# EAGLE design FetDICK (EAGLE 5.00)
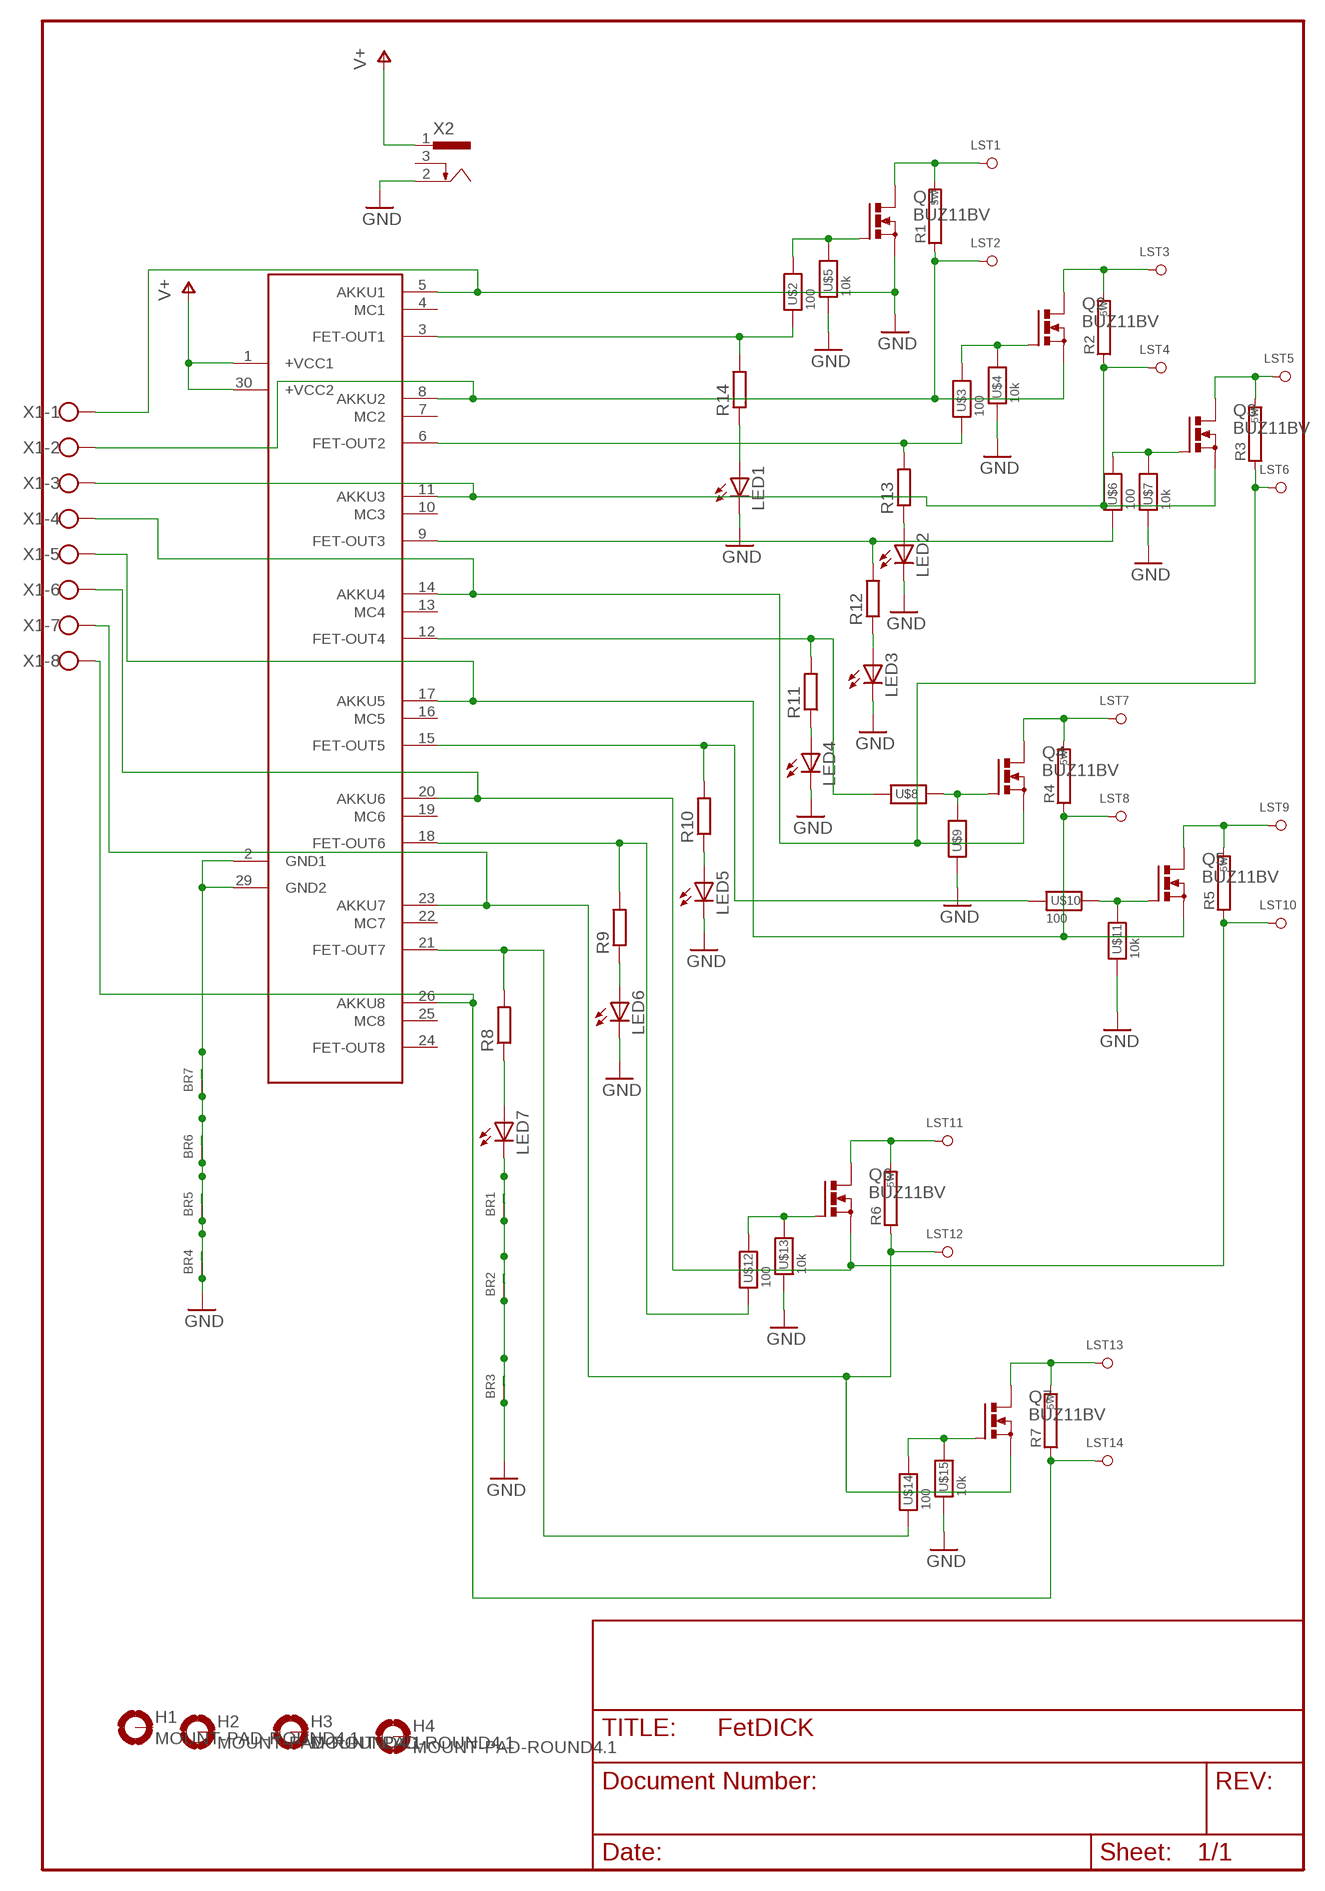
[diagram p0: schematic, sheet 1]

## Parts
BR1  BRUE3E  [BRUE3E]
BR2  BRUE3E  [BRUE3E]
BR3  BRUE3E  [BRUE3E]
BR4  BRUE3E  [BRUE3E]
BR5  BRUE3E  [BRUE3E]
BR6  BRUE3E  [BRUE3E]
BR7  BRUE3E  [BRUE3E]
H1  MOUNT-PAD-ROUND4.1  [4,1-PAD]
H2  MOUNT-PAD-ROUND4.1  [4,1-PAD]
H3  MOUNT-PAD-ROUND4.1  [4,1-PAD]
H4  MOUNT-PAD-ROUND4.1  [4,1-PAD]
LED1  LED5MM  [LED5MM]
LED2  LED5MM  [LED5MM]
LED3  LED5MM  [LED5MM]
LED4  LED5MM  [LED5MM]
LED5  LED5MM  [LED5MM]
LED6  LED5MM  [LED5MM]
LED7  LED5MM  [LED5MM]
LST1  LOETST02  [LOETST02]
LST2  LOETST02  [LOETST02]
LST3  LOETST02  [LOETST02]
LST4  LOETST02  [LOETST02]
LST5  LOETST02  [LOETST02]
LST6  LOETST02  [LOETST02]
LST7  LOETST02  [LOETST02]
LST8  LOETST02  [LOETST02]
LST9  LOETST02  [LOETST02]
LST10  LOETST02  [LOETST02]
LST11  LOETST02  [LOETST02]
LST12  LOETST02  [LOETST02]
LST13  LOETST02  [LOETST02]
LST14  LOETST02  [LOETST02]
Q1  BUZ11BV  [TO220BV]
Q2  BUZ11BV  [TO220BV]
Q3  BUZ11BV  [TO220BV]
Q4  BUZ11BV  [TO220BV]
Q5  BUZ11BV  [TO220BV]
Q6  BUZ11BV  [TO220BV]
Q7  BUZ11BV  [TO220BV]
R1  208R  [208R]
R2  208R  [208R]
R3  208R  [208R]
R4  208R  [208R]
R5  208R  [208R]
R6  208R  [208R]
R7  208R  [208R]
R8  R-EU_0207/2V  [0207/2V]
R9  R-EU_0207/2V  [0207/2V]
R10  R-EU_0207/2V  [0207/2V]
R11  R-EU_0207/2V  [0207/2V]
R12  R-EU_0207/2V  [0207/2V]
R13  R-EU_0207/2V  [0207/2V]
R14  R-EU_0207/2V  [0207/2V]
U$1  BALANCER1  [1X30]
U$2  100  R4E  [R-4E]
U$3  100  R4E  [R-4E]
U$4  10k  R4E  [R-4E]
U$5  10k  R4E  [R-4E]
U$6  100  R4E  [R-4E]
U$7  10k  R4E  [R-4E]
U$8  R4E  [R-4E]
U$9  R4E  [R-4E]
U$10  100  R4E  [R-4E]
U$11  10k  R4E  [R-4E]
U$12  100  R4E  [R-4E]
U$13  10k  R4E  [R-4E]
U$14  100  R4E  [R-4E]
U$15  10k  R4E  [R-4E]
X1  W237-08P  [W237-8P]
X2  733980-62  [733980-62]

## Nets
GND: BR1.1 BR1.2 BR2.1 BR2.2 BR3.1 BR3.2 BR4.1 BR4.2 BR5.1 BR5.2 BR6.1 BR6.2 BR7.1 BR7.2 LED1.K(C) LED2.K(C) LED3.K(C) LED4.K(C) LED5.K(C) LED6.K(C) LED7.K(C) Q1.S U$1.2(GND1) U$1.5(AKKU1) U$1.29(GND2) U$4.1 U$5.1 U$7.1 U$9.1 U$11.1 U$13.1 U$15.1 X1.1 X2.2
N$1: R14.2 U$1.3(FET-OUT1) U$2.1
N$2: Q1.G U$2.2 U$5.2
N$3: LED1.A R14.1
N$4: LST1.1 Q1.D R1.2
N$5: R13.2 U$1.6(FET-OUT2) U$3.1
N$6: LST2.1 Q2.S R1.1 U$1.8(AKKU2) X1.2
N$7: Q2.G U$3.2 U$4.2
N$9: LST3.1 Q2.D R2.2
N$10: LST4.1 Q3.S R2.1 U$1.11(AKKU3) X1.3
N$11: R12.2 U$1.9(FET-OUT3) U$6.1
N$12: Q3.G U$6.2 U$7.2
N$13: LED2.A R13.1
N$14: LST5.1 Q3.D R3.2
N$15: LST6.1 Q4.S R3.1 U$1.14(AKKU4) X1.4
N$16: R11.2 U$1.12(FET-OUT4) U$8.1
N$17: Q4.G U$8.2 U$9.2
N$19: LST7.1 Q4.D R4.2
N$20: LST8.1 Q5.S R4.1 U$1.17(AKKU5) X1.5
N$21: R10.2 U$1.15(FET-OUT5) U$10.1
N$22: Q5.G U$10.2 U$11.2
N$23: LED3.A R12.1
N$24: LST9.1 Q5.D R5.2
N$25: R8.2 U$1.21(FET-OUT7) U$14.1
N$26: R9.2 U$1.18(FET-OUT6) U$12.1
N$27: Q6.G U$12.2 U$13.2
N$28: LST10.1 Q6.S R5.1 U$1.20(AKKU6) X1.6
N$29: LST11.1 Q6.D R6.2
N$31: Q7.G U$14.2 U$15.2
N$32: LST12.1 Q7.S R6.1 U$1.23(AKKU7) X1.7
N$33: LST13.1 Q7.D R7.2
N$34: LST14.1 R7.1 U$1.26(AKKU8) X1.8
N$35: LED4.A R11.1
N$36: LED5.A R10.1
N$37: LED6.A R9.1
N$38: LED7.A R8.1
V+: U$1.1(+VCC1) U$1.30(+VCC2) X2.1
Unconnected: H1.B4,1(MOUNT) H2.B4,1(MOUNT) H3.B4,1(MOUNT) H4.B4,1(MOUNT) U$1.4(MC1) U$1.7(MC2) U$1.10(MC3) U$1.13(MC4) U$1.16(MC5) U$1.19(MC6) U$1.22(MC7) U$1.24(FET-OUT8) U$1.25(MC8) X2.3

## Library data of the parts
BR1-BR7 = raf_discrete:BRUE3E
H1-H4 = holes:MOUNT-PAD-ROUND: MOUNTING PAD, round
LED1-LED7 = led:LED: LED
LST1-LST14 = raf_connector:LOETST02
Q1-Q7 = transistor-power:BUZ11: N-CHANNEL MOS FET
R1-R7 = R-PWR:208R
R8-R14 = rcl:R-EU_: RESISTOR, European symbol
U$1 = balancer-mega8:BALANCER1
U$2-U$15 = raf_discrete:R: Standard-Widerstand 1/4W, Baugrößen 4e - 8e
X1 = con-wago-508:W237-08P: WAGO SREW CLAMP
X2 = con-conrad:73398?: FEMALE PRINT CONNECTOR Niedervolt-Steckverbinder Distributor Conrad

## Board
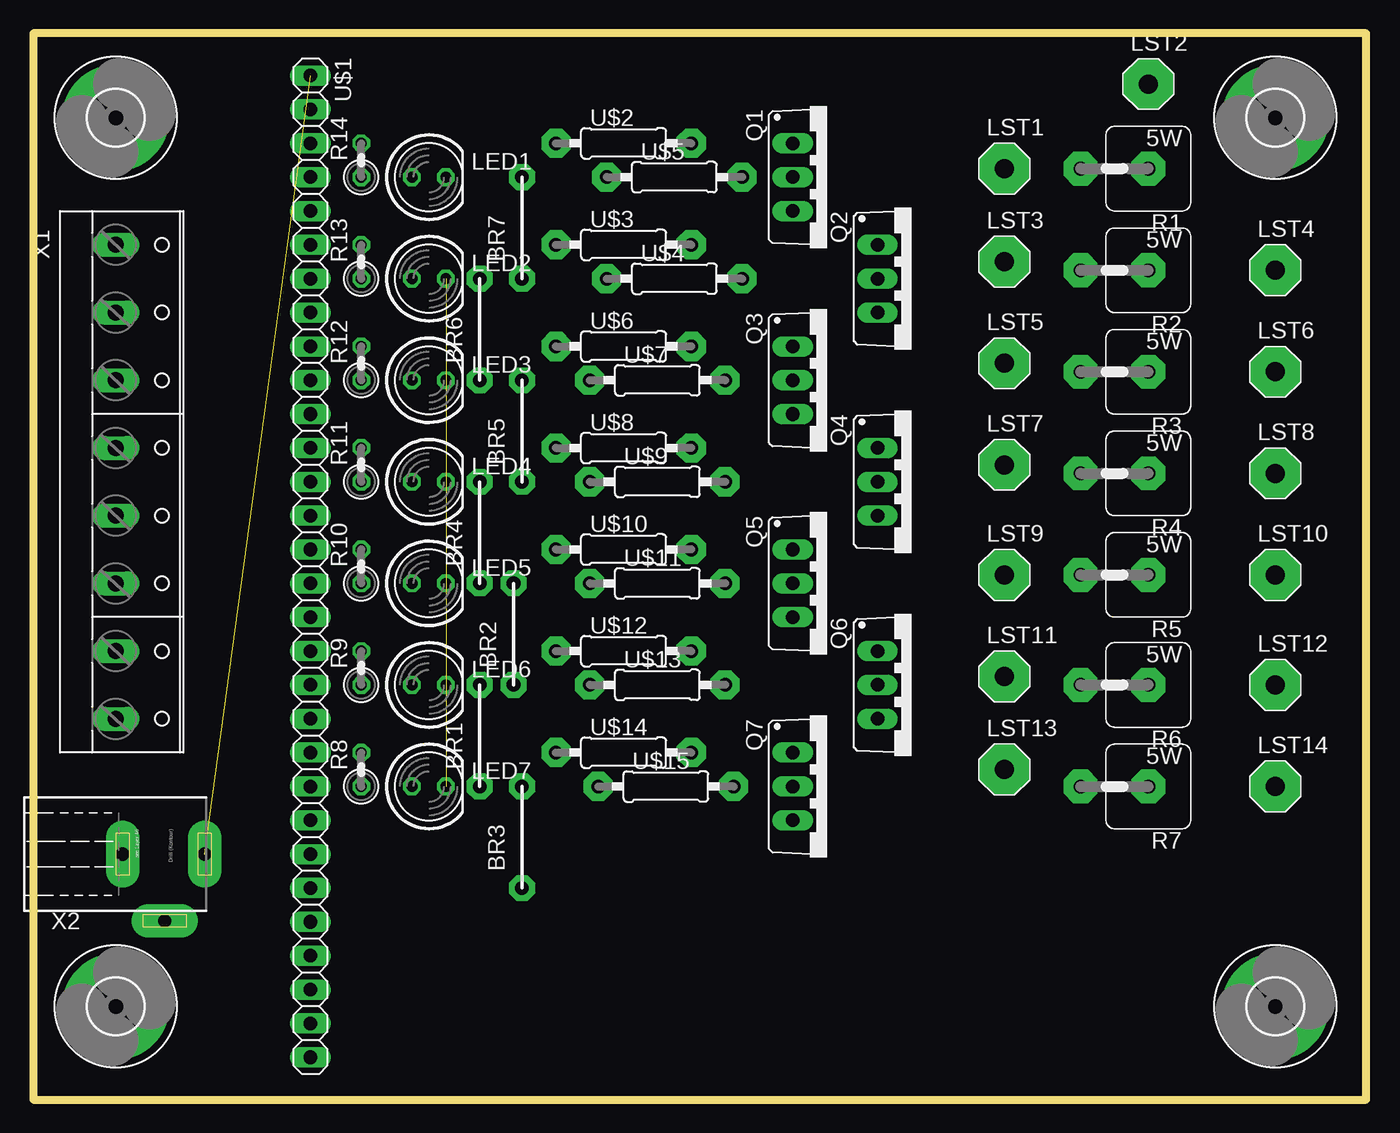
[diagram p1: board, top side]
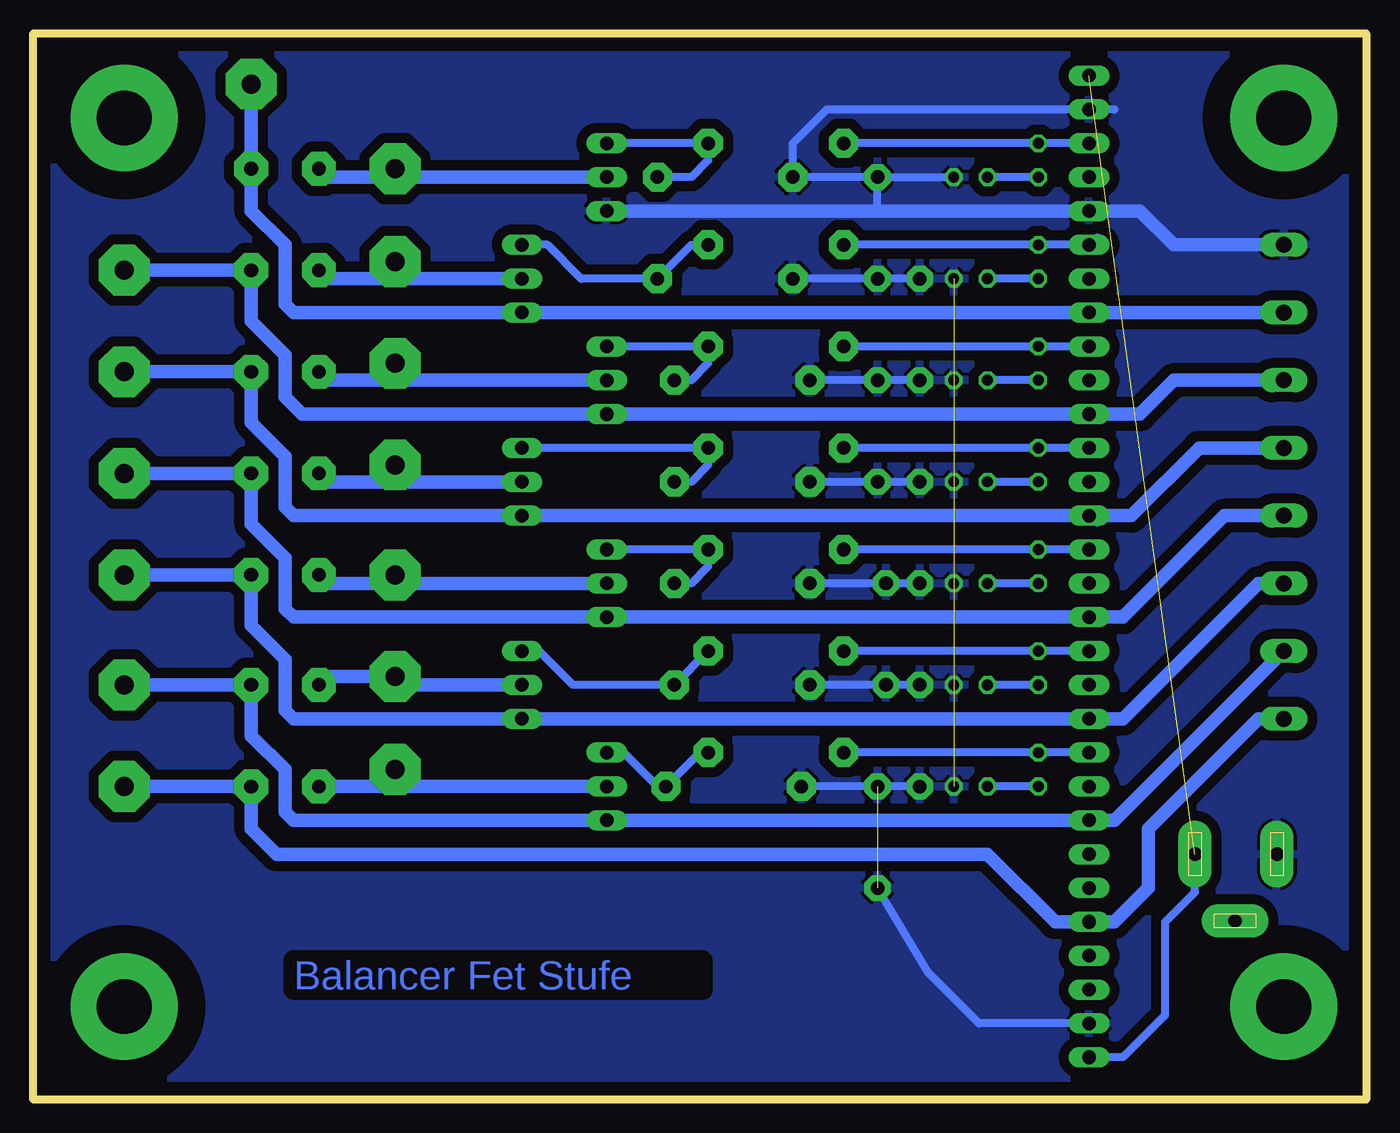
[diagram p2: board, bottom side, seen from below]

Size 100 x 80 mm. Coordinates in mm from the lower left corner, seen from the top.
Outline: 0,0 100,0 100,80 0,80 0,0
Copper layers (1*16): Top 0.035mm / dielectric 1.5mm / Bottom 0.035mm
Design rules "default *": minimum track width 10mil, minimum drill 24mil, track to track 30mil, track to pad 30mil, pad to pad 8mil, via to via 8mil, smd to smd 8mil, copper to edge 40mil, drill to drill 8mil, minimum pad ring 10mil, minimum via ring 8mil, stop-mask expansion 4mil, vias tented up to drill 0mil, thermal gap 10mil

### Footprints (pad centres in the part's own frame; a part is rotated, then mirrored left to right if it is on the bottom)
BRUE3E = drill 1.016 pad 1.93 octagon: 1 0,0; 2 7.62,0
4,1-PAD = drill 4.1 pad 8 round: B4,1 0,0
LED5MM = drill 0.813 octagon: A -1.27,0; K 1.27,0
LOETST02 = drill 1.422 pad 3.81 octagon: 1 0,0
TO220BV = drill 1.016 long: D 0,-2.54; G -2.54,-2.54; S 2.54,-2.54
208R = drill 1.016 pad 2.54 octagon: 1 -2.54,0; 2 2.54,0
0207/2V = drill 0.813 octagon: 1 -1.27,0; 2 1.27,0
1X30 = drill 1.016 long: 1 -36.83,0; 2 -34.29,0; 3 -31.75,0; 4 -29.21,0; 5 -26.67,0; 6 -24.13,0; 7 -21.59,0; 8 -19.05,0; 9 -16.51,0; 10 -13.97,0; 11 -11.43,0; 12 -8.89,0; 13 -6.35,0; 14 -3.81,0; 15 -1.27,0; 16 1.27,0; 17 3.81,0; 18 6.35,0; 19 8.89,0; 20 11.43,0; 21 13.97,0; 22 16.51,0; 23 19.05,0; 24 21.59,0; 25 24.13,0; 26 26.67,0; 27 29.21,0; 28 31.75,0; 29 34.29,0; 30 36.83,0
R-4E = drill 1.016 pad 2.184 octagon: 1 -5.08,0; 2 5.08,0
W237-8P = drill 1.194 long: 1 -17.78,-0.635; 2 -12.7,-0.635; 3 -7.62,-0.635; 4 -2.54,-0.635; 5 2.54,-0.635; 6 7.62,-0.635; 7 12.7,-0.635; 8 17.78,-0.635
733980-62 = drill 1 pad 2.5 long: 1 0,8.57; 2 0,2.42; 3 5,5.57

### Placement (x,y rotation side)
BR1  33.49,23.49 90 top
BR2  36.03,31.11 90 top
BR3  36.66,15.87 90 top
BR4  33.49,38.73 90 top
BR5  36.66,46.35 90 top
BR6  33.49,53.97 90 top
BR7  36.66,61.59 90 top
H1  6.18,6.98 0 top
H2  93.18,6.98 0 top
H3  93.18,73.66 0 top
H4  6.18,73.66 0 top
LED1  29.68,69.21 0 top
LED2  29.68,61.59 0 top
LED3  29.68,53.97 0 top
LED4  29.68,46.35 0 top
LED5  29.68,38.73 0 top
LED6  29.68,31.11 0 top
LED7  29.68,23.49 0 top
LST1  72.86,69.84 0 top
LST2  83.66,76.19 0 top
LST3  72.86,62.86 0 top
LST4  93.18,62.23 0 top
LST5  72.86,55.24 0 top
LST6  93.18,54.61 0 top
LST7  72.86,47.62 0 top
LST8  93.18,46.98 0 top
LST9  72.86,39.37 0 top
LST10  93.18,39.37 0 top
LST11  72.86,31.74 0 top
LST12  93.18,31.11 0 top
LST13  72.86,24.76 0 top
LST14  93.18,23.49 0 top
Q1  59.52,69.21 270 top
Q2  65.88,61.59 270 top
Q3  59.52,53.97 270 top
Q4  65.88,46.35 270 top
Q5  59.52,38.73 270 top
Q6  65.88,31.11 270 top
Q7  59.52,23.49 270 top
R1  81.11,69.84 180 top
R2  81.11,62.23 180 top
R3  81.11,54.61 180 top
R4  81.11,46.98 180 top
R5  81.11,39.37 180 top
R6  81.11,31.11 180 top
R7  81.11,23.49 180 top
R8  24.6,24.76 90 top
R9  24.6,32.38 90 top
R10  24.6,40 90 top
R11  24.6,47.62 90 top
R12  24.6,55.24 90 top
R13  24.6,62.86 90 top
R14  24.6,70.48 90 top
U$1  20.79,40 270 top
U$2  44.28,71.75 0 top
U$3  44.28,64.13 0 top
U$4  48.09,61.59 0 top
U$5  48.09,69.21 0 top
U$6  44.28,56.51 0 top
U$7  46.82,53.97 0 top
U$8  44.28,48.89 0 top
U$9  46.82,46.35 0 top
U$10  44.28,41.27 0 top
U$11  46.82,38.73 0 top
U$12  44.28,33.65 0 top
U$13  46.82,31.11 0 top
U$14  44.28,26.03 0 top
U$15  47.46,23.49 0 top
X1  6.82,46.35 270 top
X2  4.28,18.41 270 top

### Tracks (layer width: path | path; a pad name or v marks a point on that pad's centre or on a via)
GND  (6 unrouted)
  Bottom 0.406: 21.42,74.29 U$1.2 | BR1.2 BR2.1 | 21.42,66.67 31.58,66.67
  Bottom 0.61: U$15.1 BR3.2 BR1.1 | BR1.2 BR2.1 U$13.1 | BR4.1 BR2.2 U$11.1 | BR4.2 BR5.1 U$9.1 | BR6.1 BR5.2 U$7.1 | BR6.2 BR7.1 U$4.1 | BR7.2 U$5.1 43.02,71.75 40.48,74.29 21.42,74.29 18.88,74.29 | U$1.29 29.04,5.71 32.85,9.52 BR3.1 | BR7.2 LED1.K | 36.66,66.67 BR7.2
  Bottom 1.016: 21.42,66.67 U$1.5 | 21.42,66.67 36.66,66.67 Q1.S | 21.42,66.67 16.98,66.67 14.44,64.13 X1.1
  pour Bottom: 0.47,79.37 99.53,79.37 99.53,0.63 0.47,0.63
N$1
  Bottom 0.406: U$1.3 R14.2
  Bottom 0.61: U$2.1 R14.2 U$1.3
N$2
  Bottom 0.406: 49.37,70.48 U$2.2
  Bottom 0.61: U$2.2 Q1.G | 49.37,70.48 50.63,69.21 U$5.2
N$3
  Bottom 0.61: R14.1 LED1.A
N$4
  Bottom 1.016: Q1.D 72.86,69.21 | 72.86,69.21 77.94,69.21 R1.2 | 72.86,69.21 LST1.1
N$5
  Bottom 0.406: R13.2 U$1.6 20.15,64.77
  Bottom 0.61: U$3.1 R13.2 U$1.6
N$6
  Bottom 1.016: LST2.1 R1.1 83.66,66.67 81.11,64.13 81.11,59.69 80.48,59.05 Q2.S U$1.8 X1.2
N$7
  Bottom 0.61: U$3.2 50.63,64.13 U$4.2 58.89,61.59 61.43,64.13 Q2.G
N$9
  Bottom 1.016: Q2.D 72.86,61.59 | 72.86,61.59 77.94,61.59 R2.2 | 72.86,61.59 LST3.1
N$10
  Bottom 1.016: 93.81,62.23 LST4.1 R2.1 83.66,58.41 81.11,55.88 81.11,52.7 79.84,51.43 Q3.S U$1.11 16.98,51.43 14.44,53.97 X1.3
N$11
  Bottom 0.406: U$1.9 R12.2
  Bottom 0.61: U$6.1 R12.2 U$1.9
N$12
  Bottom 0.406: 49.37,55.24 U$6.2
  Bottom 0.61: U$6.2 Q3.G | 49.37,55.24 50.63,53.97 U$7.2
N$13
  Bottom 0.61: R13.1 LED2.A
N$14
  Bottom 1.016: Q3.D 72.86,53.97 | 72.86,53.97 77.94,53.97 R3.2 | 72.86,53.97 LST5.1
N$15
  Bottom 0.406: U$1.14 20.15,43.18
  Bottom 1.016: 93.81,53.97 LST6.1 R3.1 83.66,50.8 81.11,48.26 81.11,44.45 80.48,43.81 Q4.S U$1.14 17.61,43.81 12.54,48.89 X1.4
N$16
  Bottom 0.406: U$1.12 R11.2
  Bottom 0.61: U$8.1 R11.2 U$1.12
N$17
  Bottom 0.406: 49.37,47.62 U$8.2 | 50.63,46.35 U$9.2 52.54,46.35
  Bottom 0.61: U$8.2 Q4.G | 50.63,46.35 49.37,47.62
N$19
  Bottom 1.016: Q4.D 73.5,46.35 | 73.5,46.35 77.94,46.35 R4.2 | LST7.1 72.86,46.98 73.5,46.35
N$20
  Bottom 1.016: LST8.1 R4.1 83.66,43.18 81.11,40.64 81.11,36.83 80.48,36.19 Q5.S U$1.17 18.25,36.19 10.63,43.81 X1.5
N$21
  Bottom 0.406: U$1.15 R10.2
  Bottom 0.61: U$10.1 R10.2 U$1.15
N$22
  Bottom 0.406: 49.37,40 U$10.2 | U$11.2 52.54,38.73
  Bottom 0.61: U$10.2 Q5.G | 49.37,40 50.63,38.73 U$11.2
N$23
  Bottom 0.61: R12.1 LED3.A
N$24
  Bottom 1.016: Q5.D 73.5,38.73 | 73.5,38.73 77.94,38.73 R5.2 | 73.5,38.73 LST9.1
N$25
  Bottom 0.406: U$1.21 R8.2
  Bottom 0.61: U$1.21 U$14.1
N$26
  Bottom 0.406: U$1.18 R9.2
  Bottom 0.61: U$12.1 R9.2 U$1.18
N$27
  Bottom 0.406: 62.06,33.65 Q6.G
  Bottom 0.61: U$12.2 U$13.2 59.52,31.11 62.06,33.65
N$28
  Bottom 1.016: LST10.1 R5.1 83.66,35.55 81.11,33.02 81.11,29.2 80.48,28.57 Q6.S U$1.20 18.25,28.57 8.09,38.73 X1.6
N$29
  Bottom 1.016: Q6.D 72.22,31.11 LST11.1 77.94,31.74 R6.2
N$31
  Bottom 0.406: 50,26.03 U$14.2 | U$15.2 53.17,23.49 | 55.71,26.03 Q7.G
  Bottom 0.61: U$15.2 50,26.03 | 53.17,23.49 55.71,26.03
N$32
  Bottom 1.016: LST12.1 R6.1 83.66,27.3 81.11,24.76 81.11,21.58 80.48,20.95 Q7.S U$1.23 18.88,20.95 X1.7
N$33
  Bottom 1.016: Q7.D 72.86,23.49 | 72.86,23.49 R7.2 | 72.86,23.49 LST13.1
N$34
  Bottom 1.016: LST14.1 R7.1 83.66,20.31 81.75,18.41 28.41,18.41 23.33,13.33 U$1.26 18.88,13.33 16.34,15.87 16.34,20.31 8.09,28.57 X1.8
N$35
  Bottom 0.61: R11.1 LED4.A
N$36
  Bottom 0.61: R10.1 LED5.A
N$37
  Bottom 0.61: R9.1 LED6.A
N$38
  Bottom 0.61: R8.1 LED7.A
V+  (1 unrouted)
  Bottom 0.61: U$1.30 18.25,3.17 15.08,6.34 15.08,13.33 12.85,15.56 X2.1

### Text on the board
Bottom: Balancer Fet Stufe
